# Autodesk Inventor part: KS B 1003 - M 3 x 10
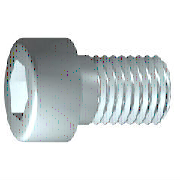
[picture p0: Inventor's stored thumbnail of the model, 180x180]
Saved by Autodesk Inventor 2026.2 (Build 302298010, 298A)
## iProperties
Created: 2025-01
Part Number: KS B 1003 - M 3 x 10
Material: 강철, 연강
Description: 6각머리 태핑 나사
Document SubType Name: Modeling
Standard: KS B 1003
Designer: work
Standards Organization: KS
Language: ko-KR
Size Designation: M 3 x 10
Categories: <MemberInstance><Categories><Category DisplayName="조임쇠" InternalName="e4da775c-781d-43d5-af7c-5136215cf5a6" Mnemonic="FSTN"><Category DisplayName="볼트" InternalN
Density: 7.85 g/cm^3
Appearance: 반연마
IsCustomPart: 1
Author: work
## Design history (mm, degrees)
workplane "Work Plane1"
fillet "Fillet2" dims "d30" = 0.1 (= R)
revolve "본체" stored, may be unused: angle "d10" = 90 deg
sketch "스케치2"
  geometry: L1 (0, -3.85)-(0, 3.85) reference; L2 (-3.85, 0)-(3.85, 0) reference; L3 (1.443, 0)-(0.722, -1.25); L4 (0.722, -1.25)-(-0.722, -1.25); L5 (-0.722, -1.25)-(-1.443, 0); L6 (-1.443, 0)-(-0.722, 1.25); L7 (-0.722, 1.25)-(0.722, 1.25); L8 (0.722, 1.25)-(1.443, 0); 2 further points
  constraints: 12 end point, 1 coincident, 1 horizontal alignment, 1 point on line, 12 other
extrude "슬롯" join sketch "스케치2" stored distance "d11" = 10; taper "d12" = 0 deg
body "Solid1"
fillet "모깎기1" dims "d17" = 0.3 (= RR)
feature "스레드" dims "d13" = 8.75 (= GEL), "d14" = 0
chamfer "모따기1" distance "d15" = 0.30673 (= -0.5 x SPD + 0.5 x GD); stored, may be unused: second distance "d16" = 0.30673 (= GUL), angle "d27" = 45 deg
sketch "스케치1"
  geometry: L1 (-0.867, 0)-(10, 0); L2 (10, 0)-(10, 1.5); L3 (10, 1.5)-(1.25, 1.5); L4 (1.25, 1.5)-(0.943, 1.5); L5 (0.943, 1.5)-(0, 1.5); L6 (0, 1.5)-(0, 2.75); L7 (0, 2.75)-(-3, 2.75); L8 (-3, 2.75)-(-3, 1.443); L9 (-3, 1.443)-(-1.7, 1.443); L10 (-1.7, 1.443)-(-0.867, 0); L11 (-5.6, 0)-(12.6, 0) reference; L12 (0, -0.55)-(0, 3.3) reference; L13 (1.25, 1.5)-(0, 1.5)
  constraints: 22 end point, 6 parallel, 2 collinear, 2 perpendicular, 1 horizontal, 1 point on line
  dimensions: "d1" = 8.75 distance from line of L3.end L2 (= GEL); "d2" = 0.30683 distance of L4.end L3.end (computed from GAL); "d3" = 3 distance between parallel lines of L8 L6 (= KOH); "d4" = 1.3 distance of L8.end L9.end (= INTI); "d5" = 60 deg angle of L10 L1; "d6" = 3 diameter of L3 L1 (= GD); "d7" = 3 diameter of L5 L1 (= BDM); "d8" = 2.88675 diameter of L9 L1 (= 1.1547 x SW); "d9" = 5.5 diameter of L7 L1 (= KOD); "d26" = 10 distance between parallel lines of L12 L2 (= NLG)
other parameters: "GD" = 3 (= NND) [user parameter; used in 2 equation terms], "NLG" = 10 [user parameter; used in 1 equation term], "GEL" = 8.75 [user parameter; used in 2 equation terms], "KOD" = 5.5 [user parameter; used in 1 equation term], "KOH" = 3 [user parameter; used in 1 equation term], "INTI" = 1.3 [user parameter; used in 1 equation term], "GAL" = 0.30673 (= 0.61345 x PTC) [user parameter; used in 1 equation term], "GUL" = 0.30673 (= 0.61345 x PTC) [user parameter; used in 1 equation term], "BDM" = 3 (= NND) [user parameter; used in 1 equation term], "SW" = 2.5 [user parameter; used in 2 equation terms], "RR" = 0.3 [user parameter; used in 1 equation term], "SPD" = 2.38655 (= NND - 1.2269 x PTC) [user parameter; used in 1 equation term], "d19" = 0, "d28" = 0, "d29" = 0, "R" = 0.1 [user parameter; used in 1 equation term], "PHH" = 0.1 [user parameter], "GD1" = 2.38655 (= THREADDIA - 1.2269 x PTC) [user parameter], "THREADDIA" = 3 [user parameter; used in 1 equation term], "FAWI" = 45 deg [user parameter], "PTC" = 0.5 [user parameter; used in 5 equation terms], "NND" = 3 [user parameter; used in 3 equation terms], "TOA" = 30 deg [user parameter], "E0" = 2.8875 (= 1.155 x SW) [user parameter]
